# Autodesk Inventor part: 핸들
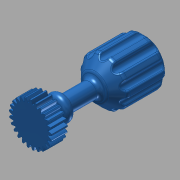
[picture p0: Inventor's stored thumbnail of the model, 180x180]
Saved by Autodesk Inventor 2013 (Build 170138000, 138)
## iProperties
Created: 2017-04
Part Number: 핸들
Material: 강철, 연강
Document SubType Name: Modeling
Designer: mduedu
Categories: <?xml version="1.0" encoding="UTF-16"?> <MemberInstance><Categories><FamilyTemplate><FamilyTemplateParameter ValueType="xs:double" Id="1" ObjectReferenceKey="da
Density: 1 g/cm^3
CustomPartVersion: 1
Author: mduedu
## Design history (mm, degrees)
sketch "Sketch1"
  geometry: C1 r 13.5 at (0, 0)
  constraints: 1 centre point
  dimensions: "d0" = 27 diameter of C1 (= da_da)
extrude "Extrusion1" new body sketch "Sketch1" distance "d1" = 10 (= da_b); taper "d2" = 0 deg
workplane "Work Plane2"
sketch "Sketch2"
  geometry: C1 r 13.5 at (0, 0) reference; C2 r 12.5 at (0, 0)
  constraints: 1 centre point, 1 coincident
  dimensions: "d3" = 25 diameter of C2 (= da_dw)
feature "피치 지름" sketch "Sketch2" dims "d4" = 10, "d5" = 0
workplane "Work Plane8"
workplane "Work Plane9"
feature "스퍼 기어" dims "da_b" = 10, "da_d" = 25, "da_aw" = 25, "da_da" = 27, "da_df" = 22.5, "da_dw" = 25, angle "da_beta" = 0 deg, "da_lefttooth" = 0, "da_righttooth" = 0
sketch "스케치3"
  geometry: C1 r 5 at (0, 0); 1 further point
  constraints: 1 centre point, 1 coincident
  dimensions: "d49" = 10 diameter of C1
extrude "돌출2" join sketch "스케치3" distance "d50" = 60; taper "d51" = 0 deg
sketch "스케치4"
  geometry: C1 r 15 at (0, 0); 1 further point
  constraints: 1 centre point, 1 coincident
  dimensions: "d52" = 30 diameter of C1
extrude "돌출3" join sketch "스케치4" distance "d53" = 30; taper "d54" = 0 deg
chamfer "모따기1" distance "d55" = 7; stored, may be unused: second distance "d56" = 2, angle "d57" = 45 deg
sketch "스케치5"
  geometry: L1 (0, 2.2)-(0, -13.2) reference; L2 (0, -5)-(8, -5); L3 (8, -5)-(8, -11); L4 (8, -11)-(0, -11); L5 (0, -11)-(0, -5); 1 further point
  constraints: 8 end point, 2 parallel, 1 horizontal, 1 perpendicular, 1 point on line
  dimensions: "d58" = 5 distance from line of L2 point (0, 0); "d59" = 6 distance of L2.end L3.end; "d60" = 16 diameter of L3 L1
revolve "회전1" sketch "스케치5" stored, may be unused: angle "d61" = 90 deg
fillet "모깎기1" dims "d62" = 3
fillet "모깎기2" dims "d65" = 3
sketch "스케치9"
  geometry: L1 (15, -60)-(-15, -60) reference; L2 (0, -60)-(0, 0); L3 (0, -66.771)-(0, -60); A1 r 20 centre (0, -46.771) between (0, -66.771) and (15, -60)
  constraints: 4 end point, 2 point on circle, 1 centre point, 1 collinear, 1 line through centre, 1 midpoint, 1 perpendicular
  dimensions: "d84" = 20 radius of A1
revolve "회전4" sketch "스케치9" stored, may be unused: angle "d86" = 90 deg
fillet "모깎기3" dims "d72" = 3
sketch "스케치6"
  geometry: C1 r 2.5 at (0, 15); 2 further points
  constraints: 2 vertical alignment, 1 centre point, 1 other
  dimensions: "d66" = 5 diameter of C1
extrude "돌출4" cut sketch "스케치6" stored distance "d67" = 60; taper "d68" = 0 deg
fillet "모깎기4" dims "d73" = 1
node "작업 평면12"
sketch "스케치10"
  geometry: C1 r 6 at (0, 0); 1 further point
  constraints: 1 centre point, 1 coincident
  dimensions: "d87" = 12 diameter of C1
extrude "돌출5" cut sketch "스케치10" distance "d88" = 5; taper "d89" = 0 deg
fillet "모깎기5" dims "d90" = 1
body "Solid1"
pattern_circular "원형 패턴2" dims angle "d75" = 360 deg
body "Srf1"
other parameters: "d16" = 25 (= da_aw), "d17" = 0, "d34" = 1.25664 (computed from da_z), "d39" = 0, "d41" = 0, "d43" = 25 (= da_aw), "d46" = 25 (= da_aw), "d47" = 0, "d48" = 0
